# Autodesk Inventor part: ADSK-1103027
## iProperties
Shininess: 92.0
Length Units: 11272
Angle Units: 11279
Time Units: 11290
Mass Units: 11286
Length Display Precision: 4
Angle Display Precision: 2
Compacted: True
Created: 2000-06
Part Number: ADSK-1103027
Document SubType Name: Modeling
Description: 20 TOOTH CLUTCH GEAR
Mass: 2.75185 g
Surface Area: 8.98572 cm^2
Volume: 0.351001 cm^3
Density: 7.84 g/cm^3
Material: Steel, High Strength Low Alloy
Density: 0.0
Volumn: 0.0
Area: 0.0
PropertySet Name: Model Information
Control State: 0
Master: False
Checked Out: False
Author: Autodesk, Inc.
